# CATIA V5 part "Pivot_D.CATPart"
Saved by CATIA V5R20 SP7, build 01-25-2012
Part number: Pivot_D
Bounding box of the stored display mesh (mm): x -2.5 to 2.5, y 27.5 to 32.5, z -6 to 6
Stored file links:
  D:\IFMA\COURS\2A\projet balance IAO\catia\Pivot_D.CATPart
  D:\IFMA\COURS\2A\projet balance IAO\catia\Ass_projet_balance.CATProduct
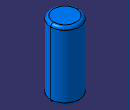
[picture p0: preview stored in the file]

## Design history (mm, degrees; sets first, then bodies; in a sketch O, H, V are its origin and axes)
Set1
  Plane1 "Plan.KDAF": linked copy from another document
  Point1 "Point.D": linked copy from another document
Body1 (main body)
  Sketch1 on Plane1, origin (0, 0, 0), H (1, 0, 0), V (0, 1, 0)
    circle A1 centre (0, 30) radius 2.5
    point P1 (0, 30)
    reference projected point E1 (0, 30) from Point1
    radius A1 = 2.5
    coincidence: P1 E1
  Pad1: profile Sketch1, direction (0, 0, 1), length 6, mirrored extent
  Fillet1: radius 0.5, on edge [face of Pad1 from Sketch1.A1 | end face of Pad1]; edge [start face of Pad1 | face of Pad1 from Sketch1.A1]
